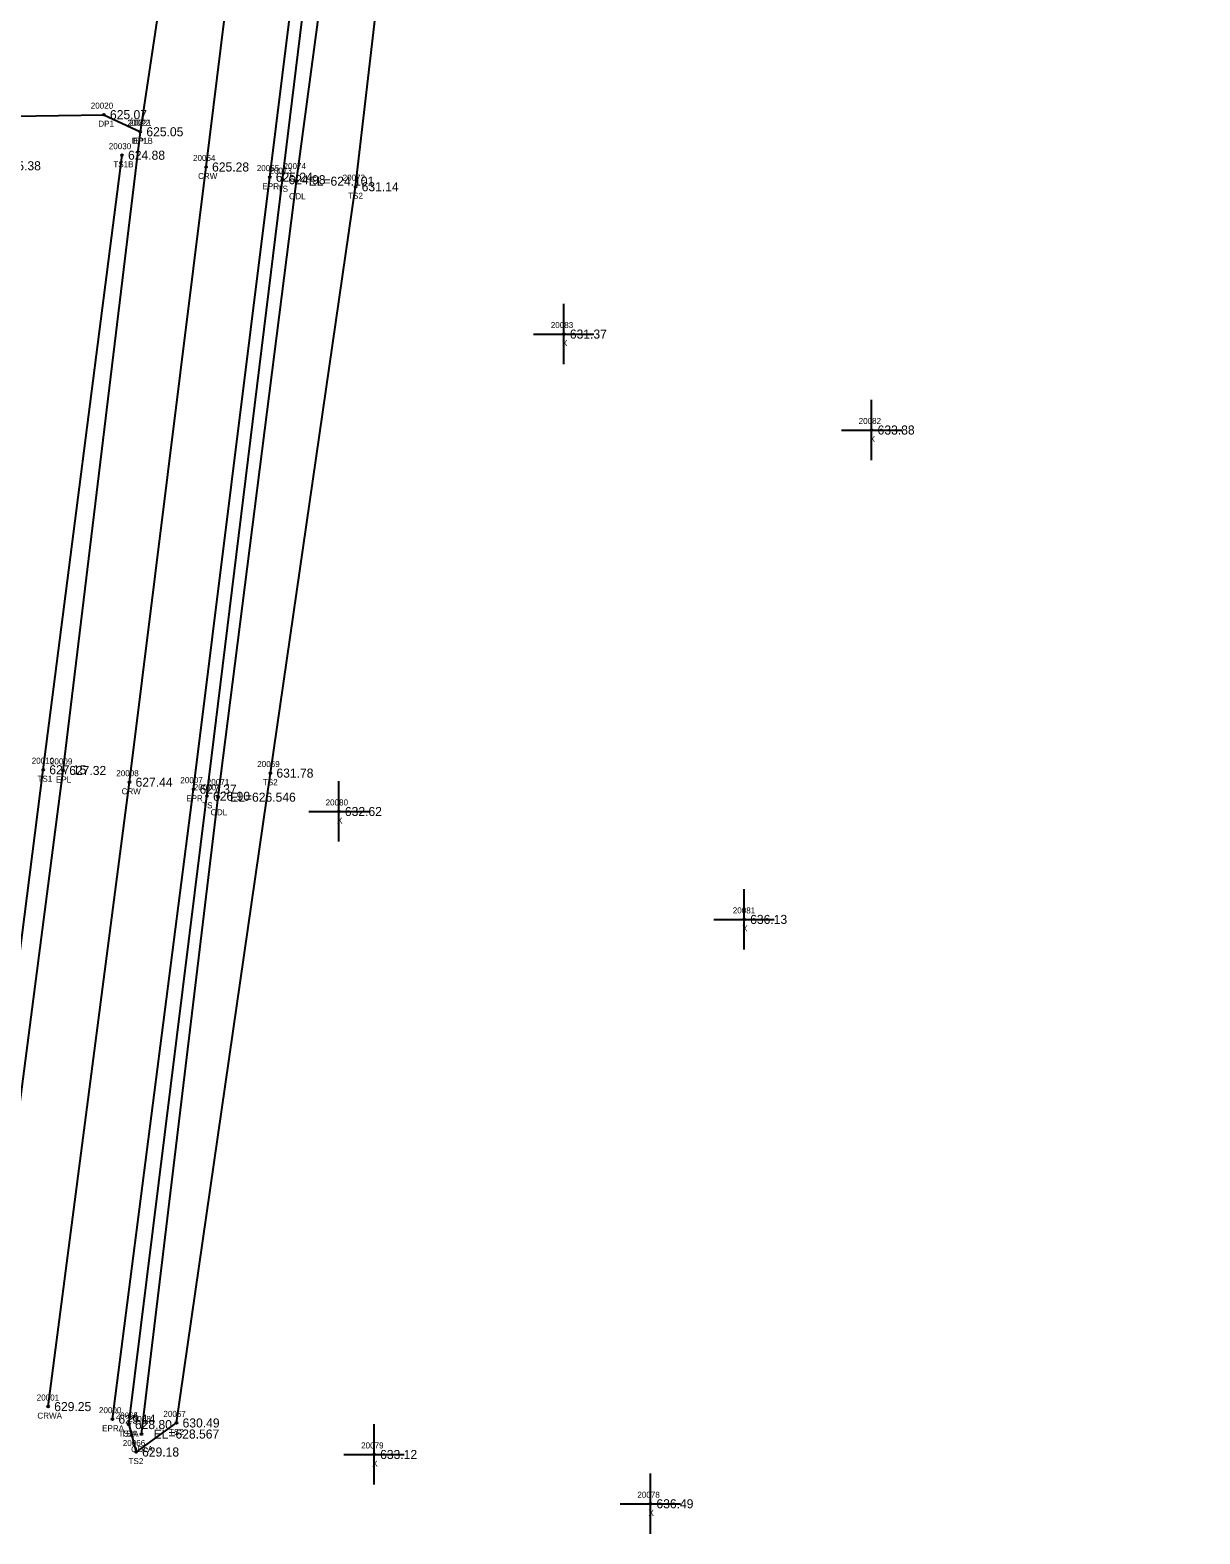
# Model space of a CAD drawing. Extents: x 1695443 to 1696344, y 1087542 to 1090645.
# Drawn here: x 1695866.2 to 1696060.1, y 1087542.3 to 1087791.5 of the extents above; entities that cross this region are included whole.
import ezdxf

# ---------------------------------------------------------------- set-up
doc = ezdxf.new("R2010")
doc.units = 0
for name, color, linetype in [('RD_DTM_BkLn1', 7, 'Continuous'), ('RD_DTM_BkLn2', 7, 'Continuous'), ('RD_DTM_BkLn_txCode', 7, 'Continuous'), ('RD_EX_Driveway', 7, 'Continuous'), ('RD_EX_Driveway_txCode', 7, 'Continuous'), ('RD_EX_H2O', 7, 'Continuous'), ('RD_EX_H2O_txCode', 7, 'Continuous'), ('RD_EX_Misc', 7, 'Continuous'), ('RD_EX_Misc_txCode', 7, 'Continuous'), ('RD_EX_Road', 7, 'Continuous'), ('RD_EX_Road_txCode', 7, 'Continuous'), ('RD_EX_TX_Driveway_ELEV', 7, 'Continuous'), ('RD_EX_TX_H2O_ELEV', 7, 'Continuous'), ('RD_EX_TX_Misc_ELEV', 7, 'Continuous'), ('RD_EX_TX_Road_ELEV', 7, 'Continuous'), ('RD_HC_Survey_ELEV', 7, 'Continuous'), ('RD_HC_Survey_txCode', 7, 'Continuous'), ('RD_SMD_Locator', 7, 'Continuous')]:
    doc.layers.add(name, color=color, linetype=linetype)

msp = doc.modelspace()

# ---------------------------------------------------------------- linework, layer by layer
at = {"layer": 'RD_DTM_BkLn1'}
msp.add_lwpolyline([(1695869.23, 1087563.38), (1695882.71, 1087666.87), (1695895.39, 1087768.85), (1695908.05, 1087871.3), (1695919.71, 1087974.19), (1695925.35, 1088026.13), (1695931.27, 1088077.73), (1695937.88, 1088128.75), (1695945.4, 1088182.97), (1695952.48, 1088232.38), (1695961.74, 1088286.36), (1695971.36, 1088336.92), (1695982.91, 1088390.82), (1696009.16, 1088497.22), (1696035.45, 1088601.7), (1696045.5, 1088655.66), (1696049.03, 1088705.78), (1696045.47, 1088756.42), (1696033.82, 1088809.1), (1696016.78, 1088855.71), (1695990.89, 1088906.17), (1695964.41, 1088947.39), (1695931.21, 1088992.88)], dxfattribs=at)
at = {"layer": 'RD_DTM_BkLn2'}
for points in [[(1695882.6, 1087560.4), (1695895.55, 1087664.54), (1695908.06, 1087766.74), (1695920.67, 1087869.68), (1695933.47, 1087972.17), (1695938.06, 1088020.68), (1695943.39, 1088076.15), (1695950.93, 1088126.12), (1695958.62, 1088180.79), (1695967.59, 1088232.03), (1695975.32, 1088283.22), (1695985.14, 1088336.17), (1695996.59, 1088387.88), (1696023.18, 1088492.82), (1696049.23, 1088599.85), (1696058.32, 1088654.25)], [(1695882.6, 1087560.4), (1695883.79, 1087555.85), (1695890.5, 1087560.67), (1695906.06, 1087668.38), (1695920.19, 1087765.58), (1695932.4, 1087870.37), (1695944.02, 1087970.73), (1695947.56, 1088017.12), (1695952.59, 1088072.2), (1695957.06, 1088113.91)], [(1695855.21, 1087565.36), (1695868.41, 1087668.94), (1695881.46, 1087770.8)]]:
    msp.add_lwpolyline(points, dxfattribs=at)
at = {"layer": 'RD_EX_Driveway'}
msp.add_lwpolyline([(1695771.6, 1087768.24), (1695801.31, 1087763.3), (1695804.87, 1087768.36), (1695808.93, 1087769.91), (1695844.56, 1087776.98), (1695878.47, 1087777.52), (1695884.5, 1087774.69)], dxfattribs=at)
at = {"layer": 'RD_EX_H2O'}
msp.add_lwpolyline([(1695884.7, 1087558.83), (1695897.39, 1087664.39), (1695910.4, 1087766.5), (1695924.17, 1087869.12), (1695936.94, 1087971.73), (1695941.17, 1088019.96), (1695947.61, 1088073.49), (1695957.06, 1088113.91)], dxfattribs=at)
at = {"layer": 'RD_EX_Misc'}
for p, q in [((1695954.7, 1087736.15), (1695954.7, 1087746.15)), ((1695949.7, 1087741.15), (1695959.7, 1087741.15)), ((1696005.72, 1087720.25), (1696005.72, 1087730.25)), ((1696000.72, 1087725.25), (1696010.72, 1087725.25)), ((1695917.41, 1087657.02), (1695917.41, 1087667.02)), ((1695912.41, 1087662.02), (1695922.41, 1087662.02)), ((1695984.59, 1087639.13), (1695984.59, 1087649.13)), ((1695979.59, 1087644.13), (1695989.59, 1087644.13)), ((1695923.25, 1087550.44), (1695923.25, 1087560.44)), ((1695918.25, 1087555.44), (1695928.25, 1087555.44)), ((1695969.05, 1087542.27), (1695969.05, 1087552.27)), ((1695964.05, 1087547.27), (1695974.05, 1087547.27))]:
    msp.add_line(p, q, dxfattribs=at)
at = {"layer": 'RD_EX_Road'}
for points in [[(1695879.87, 1087561.29), (1695893.33, 1087665.71), (1695905.96, 1087767.16), (1695918.66, 1087869.54), (1695930.87, 1087972.82), (1695936.26, 1088023.68), (1695942.14, 1088076.32), (1695948.07, 1088128.17), (1695955.04, 1088181.4), (1695962.88, 1088230.72), (1695971.68, 1088284.64), (1695982.02, 1088336.12), (1695993.28, 1088388.48), (1696018.75, 1088494.48), (1696045.23, 1088599.95), (1696055.72, 1088654.41), (1696060.15, 1088705.35), (1696055.83, 1088758.02), (1696044.01, 1088812.16), (1696026.4, 1088860.33), (1696000.41, 1088911.48), (1695972.46, 1088953.82), (1695939.48, 1088998.73), (1695931.21, 1088992.88)], [(1695858.19, 1087564.9), (1695871.71, 1087668.82), (1695884.5, 1087774.69), (1695887.48, 1087794.2), (1695897.57, 1087873.43), (1695908.92, 1087975.76), (1695914.49, 1088029.24), (1695917.65, 1088054.8), (1695920.27, 1088079.09), (1695926.98, 1088130.26), (1695934.75, 1088185.09), (1695942.15, 1088234.62), (1695951.36, 1088288.06), (1695961.48, 1088338.41), (1695972.86, 1088394.13), (1695998.53, 1088499.67), (1696024.81, 1088603.86), (1696034.83, 1088656.78)]]:
    msp.add_lwpolyline(points, dxfattribs=at)
at = {"layer": 'RD_SMD_Locator'}
for centre in [(1695878.47, 1087777.52), (1695884.5, 1087774.69), (1695884.5, 1087774.69), (1695881.46, 1087770.8), (1695895.39, 1087768.85), (1695905.96, 1087767.16), (1695908.06, 1087766.74), (1695910.4, 1087766.5), (1695920.19, 1087765.58), (1695954.7, 1087741.15), (1696005.72, 1087725.25), (1695868.41, 1087668.94), (1695871.71, 1087668.82), (1695882.71, 1087666.87), (1695906.06, 1087668.38), (1695893.33, 1087665.71), (1695895.55, 1087664.54), (1695897.39, 1087664.39), (1695917.41, 1087662.02), (1695984.59, 1087644.13), (1695869.23, 1087563.38), (1695879.87, 1087561.29), (1695882.6, 1087560.4), (1695882.6, 1087560.4), (1695890.5, 1087560.67), (1695884.7, 1087558.83), (1695883.79, 1087555.85), (1695923.25, 1087555.44), (1695969.05, 1087547.27)]:
    msp.add_circle(centre, 0.15, dxfattribs=at)

# ---------------------------------------------------------------- texts
at = {"layer": 'RD_DTM_BkLn_txCode'}
for s, p in [('20030', (1695879.27, 1087771.8)), ('TS1B', (1695880.03, 1087768.8)), ('20073', (1695905.9, 1087767.74)), ('20072', (1695918.03, 1087766.58)), ('TS', (1695907.27, 1087764.74)), ('TS2', (1695918.95, 1087763.58)), ('20010', (1695866.49, 1087669.94)), ('20069', (1695903.88, 1087669.38)), ('TS1', (1695867.45, 1087666.94)), ('20070', (1695893.35, 1087665.54)), ('TS2', (1695904.82, 1087666.38)), ('TS', (1695894.75, 1087662.54)), ('20064', (1695880.42, 1087561.4)), ('20065', (1695880.42, 1087561.4)), ('20067', (1695888.32, 1087561.67)), ('TS2A', (1695880.87, 1087558.4)), ('TSA', (1695881.32, 1087558.4)), ('TS2', (1695889.25, 1087558.67)), ('20066', (1695881.59, 1087556.85)), ('TS2', (1695882.55, 1087553.85))]:
    msp.add_text(s, height=1, dxfattribs=at).set_placement(p)
at = {"layer": 'RD_EX_Driveway_txCode'}
for s, p in [('20020', (1695876.28, 1087778.52)), ('DP1', (1695877.53, 1087775.52)), ('20021', (1695882.63, 1087775.69)), ('DP1B', (1695883.09, 1087772.69))]:
    msp.add_text(s, height=1, dxfattribs=at).set_placement(p)
at = {"layer": 'RD_EX_H2O_txCode'}
for s, p in [('20074', (1695908.24, 1087768.5)), ('ODL', (1695909.15, 1087763.5)), ('20071', (1695895.52, 1087666.39)), ('ODL', (1695896.15, 1087661.39)), ('20068', (1695882.52, 1087560.83)), ('ODLA', (1695882.97, 1087555.83))]:
    msp.add_text(s, height=1, dxfattribs=at).set_placement(p)
at = {"layer": 'RD_EX_Misc_txCode'}
for s, p in [('20083', (1695952.54, 1087742.15)), ('X', (1695954.39, 1087739.15)), ('20082', (1696003.57, 1087726.25)), ('X', (1696005.41, 1087723.25)), ('20080', (1695915.21, 1087663.02)), ('X', (1695917.1, 1087660.02)), ('20081', (1695982.71, 1087645.13)), ('X', (1695984.27, 1087642.13)), ('20079', (1695921.1, 1087556.44)), ('X', (1695922.94, 1087553.44)), ('20078', (1695966.89, 1087548.27)), ('X', (1695968.73, 1087545.27))]:
    msp.add_text(s, height=1, dxfattribs=at).set_placement(p)
at = {"layer": 'RD_EX_Road_txCode'}
for s, p in [('20022', (1695882.35, 1087775.69)), ('EPL', (1695883.3, 1087772.69)), ('20055', (1695903.8, 1087768.16)), ('EPR', (1695904.73, 1087765.16)), ('20009', (1695869.51, 1087669.82)), ('EPL', (1695870.51, 1087666.82)), ('20007', (1695891.13, 1087666.71)), ('EPR', (1695892.1, 1087663.71)), ('20000', (1695877.64, 1087562.29)), ('EPRA', (1695878.16, 1087559.29))]:
    msp.add_text(s, height=1, dxfattribs=at).set_placement(p)
at = {"layer": 'RD_EX_TX_Driveway_ELEV'}
for s, p in [('625.07', (1695879.47, 1087776.77)), ('625.05', (1695885.5, 1087773.94))]:
    msp.add_text(s, height=1.5, dxfattribs=at).set_placement(p)
at = {"layer": 'RD_EX_TX_H2O_ELEV'}
for s, p in [('EL=624.101', (1695912.4, 1087765.75)), ('EL=626.546', (1695899.39, 1087663.64)), ('EL=628.567', (1695886.7, 1087558.08))]:
    msp.add_text(s, height=1.5, dxfattribs=at).set_placement(p)
at = {"layer": 'RD_EX_TX_Misc_ELEV'}
for s, p in [('624.88', (1695882.46, 1087770.05)), ('625.38', (1695861.88, 1087768.3)), ('624.98', (1695909.06, 1087765.99)), ('631.14', (1695921.19, 1087764.83)), ('631.37', (1695955.7, 1087740.4)), ('633.88', (1696006.72, 1087724.5)), ('627.15', (1695869.41, 1087668.19)), ('631.78', (1695907.06, 1087667.63)), ('626.90', (1695896.55, 1087663.79)), ('632.62', (1695918.41, 1087661.27)), ('636.13', (1695985.59, 1087643.38)), ('628.80', (1695883.6, 1087559.65)), ('628.80', (1695883.6, 1087559.65)), ('630.49', (1695891.5, 1087559.92)), ('629.18', (1695884.79, 1087555.1)), ('633.12', (1695924.25, 1087554.69)), ('636.49', (1695970.05, 1087546.52))]:
    msp.add_text(s, height=1.5, dxfattribs=at).set_placement(p)
at = {"layer": 'RD_EX_TX_Road_ELEV'}
for s, p in [('625.05', (1695885.5, 1087773.94)), ('625.24', (1695906.96, 1087766.41)), ('627.32', (1695872.71, 1087668.07)), ('627.37', (1695894.33, 1087664.96)), ('629.14', (1695880.87, 1087560.54))]:
    msp.add_text(s, height=1.5, dxfattribs=at).set_placement(p)
at = {"layer": 'RD_HC_Survey_ELEV'}
for s, p in [('625.28', (1695896.39, 1087768.1)), ('627.44', (1695883.71, 1087666.12)), ('629.25', (1695870.23, 1087562.63))]:
    msp.add_text(s, height=1.5, dxfattribs=at).set_placement(p)
at = {"layer": 'RD_HC_Survey_txCode'}
for s, p in [('20054', (1695893.23, 1087769.85)), ('CRW', (1695894.07, 1087766.85)), ('20008', (1695880.51, 1087667.87)), ('CRW', (1695881.39, 1087664.87)), ('20001', (1695867.32, 1087564.38)), ('CRWA', (1695867.43, 1087561.38))]:
    msp.add_text(s, height=1, dxfattribs=at).set_placement(p)

doc.saveas('drawing.dxf')
